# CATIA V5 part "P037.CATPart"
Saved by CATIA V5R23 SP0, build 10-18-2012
Part number: P037
Definition: Vis hc H5 10
Description: Vis hc H5 10 à bout pointu
Bounding box of the stored display mesh (mm): x -1.988 to 1.988, y -1.988 to 1.988, z -12 to 0
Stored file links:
  C:\wamp\www\COURS\CONCEPTION GMP1\TITRE 02-SEMESTRE 2\03-TP7-PRESSE MECANIQUE\eleve\P037.CATPart
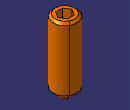
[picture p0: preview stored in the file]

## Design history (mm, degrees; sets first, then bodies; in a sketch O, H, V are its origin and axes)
Body1 (main body)
  Solid1: solid without history
  Thread1: diameter 4, depth 10.5, pitch 0.7, on face of Solid1, from face of Solid1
